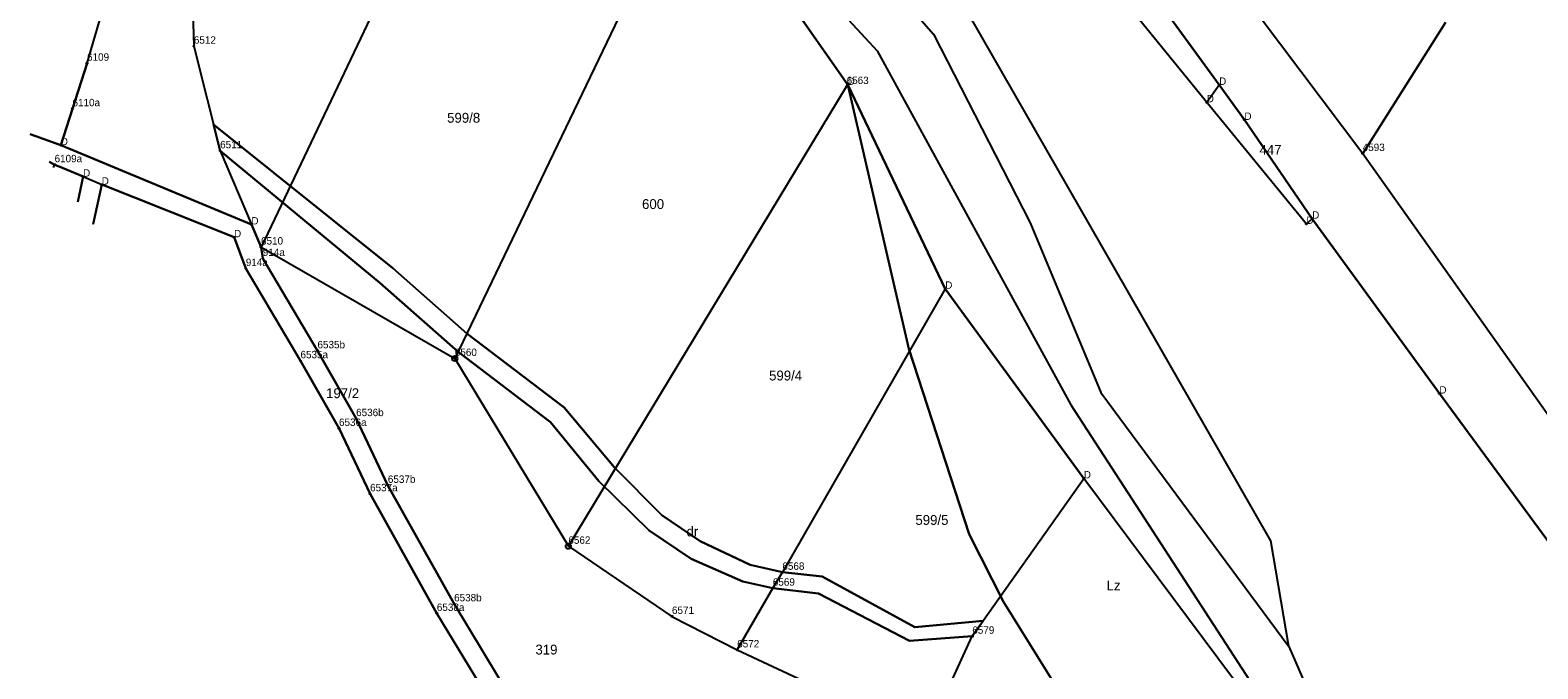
# Model space of a CAD drawing. Extents: x 7465393 to 7466459, y 5491258 to 5492404.
# Drawn here: x 7465732.5 to 7465961.5, y 5491598.3 to 5491695.3 of the extents above; entities that cross this region are included whole.
import ezdxf

# ---------------------------------------------------------------- set-up
doc = ezdxf.new("R2010")
doc.units = 0
for name, color, linetype in [('202-punkt graniczny', 7, 'Continuous'), ('202-punkt graniczny-Atr103', 7, 'Continuous'), ('203-punkt graniczny', 7, 'Continuous'), ('203-punkt graniczny-Atr103', 7, 'Continuous'), ('210-oznaczenie konturu użytku gruntowego', 7, 'Continuous'), ('211-numer działki ewidencyjnej', 7, 'Continuous'), ('217-kontur klasyfikacyjny', 7, 'Continuous'), ('218-kontur użytku gruntowego', 7, 'Continuous'), ('219-działka ewidencyjna', 7, 'Continuous')]:
    doc.layers.add(name, color=color, linetype=linetype)

# ---------------------------------------------------------------- blocks, each defined once
blk = doc.blocks.new('203')
blk.add_circle((0, 0), 0.09)
blk = doc.blocks.new('202')
blk.add_circle((0, 0), 0.4)

msp = doc.modelspace()

# ---------------------------------------------------------------- linework, layer by layer
at = {"layer": '217-kontur klasyfikacyjny'}
for points in [[(7465856.67, 5491687), (7465839.13, 5491712.1)], [(7465741.16, 5491690.28), (7465746.98, 5491710.25)], [(7465919.15, 5491697.5), (7465934.88, 5491676.57)], [(7465737.18, 5491677.85), (7465741.16, 5491690.28)], [(7465865.97, 5491646.94), (7465856.67, 5491687)], [(7465732.52, 5491679.49), (7465737.18, 5491677.85)], [(7465760.36, 5491681), (7465787.62, 5491659.17)], [(7465761.37, 5491676.99), (7465760.36, 5491681)], [(7465737.18, 5491677.85), (7465766.12, 5491665.8)], [(7465736.23, 5491674.88), (7465735.46, 5491675.31)], [(7465736.94, 5491674.58), (7465736.23, 5491674.88)], [(7465785.63, 5491656.92), (7465761.37, 5491676.99)], [(7465934.88, 5491676.57), (7465947.13, 5491659.3)], [(7465740.56, 5491673.06), (7465736.94, 5491674.58)], [(7465739.74, 5491669.23), (7465740.56, 5491673.06)], [(7465743.39, 5491671.85), (7465742.1, 5491665.87)], [(7465763.49, 5491663.86), (7465743.39, 5491671.85)], [(7465766.12, 5491665.8), (7465767.58, 5491662.37)], [(7465765.27, 5491659.12), (7465763.49, 5491663.86)], [(7465767.58, 5491662.37), (7465767.85, 5491660.64)], [(7465773.57, 5491645.11), (7465765.27, 5491659.12)], [(7465767.85, 5491660.64), (7465776.15, 5491646.63)], [(7465787.62, 5491659.17), (7465798.83, 5491649.24)], [(7465947.13, 5491659.3), (7465963.15, 5491636.73)], [(7465797.51, 5491646.48), (7465785.63, 5491656.92)], [(7465798.83, 5491649.24), (7465813.6, 5491638)], [(7465779.42, 5491634.84), (7465773.57, 5491645.11)], [(7465776.15, 5491646.63), (7465782.02, 5491636.32)], [(7465811.56, 5491635.78), (7465797.51, 5491646.48)], [(7465875.12, 5491618.79), (7465865.97, 5491646.94)], [(7465782.02, 5491636.32), (7465786.84, 5491626.19)], [(7465813.6, 5491638), (7465821.26, 5491628.88)], [(7465784.14, 5491624.91), (7465779.42, 5491634.84)], [(7465818.88, 5491626.83), (7465811.56, 5491635.78)], [(7465826.53, 5491619.32), (7465818.88, 5491626.83)], [(7465821.26, 5491628.88), (7465828.42, 5491621.66)], [(7465794.28, 5491606.75), (7465784.14, 5491624.91)], [(7465786.84, 5491626.19), (7465796.9, 5491608.21)], [(7465828.42, 5491621.66), (7465834.24, 5491617.72)], [(7465832.9, 5491615.04), (7465826.53, 5491619.32)], [(7465834.24, 5491617.72), (7465841.86, 5491614.12)], [(7465880.35, 5491608.51), (7465875.12, 5491618.79)], [(7465840.74, 5491611.57), (7465832.9, 5491615.04)], [(7465841.86, 5491614.12), (7465846.75, 5491612.99)], [(7465846.75, 5491612.99), (7465852.81, 5491612.35)], [(7465845.3, 5491610.58), (7465840.74, 5491611.57)], [(7465852.81, 5491612.35), (7465866.86, 5491604.67)], [(7465852.25, 5491609.79), (7465845.3, 5491610.58)], [(7465866.06, 5491602.58), (7465852.25, 5491609.79)], [(7465898.65, 5491579.07), (7465880.35, 5491608.51)], [(7465803.27, 5491591.89), (7465794.28, 5491606.75)], [(7465796.9, 5491608.21), (7465805.83, 5491593.45)], [(7465866.86, 5491604.67), (7465877.24, 5491605.61)], [(7465877.24, 5491605.61), (7465875.59, 5491603.28)], [(7465875.59, 5491603.28), (7465866.06, 5491602.58)]]:
    msp.add_lwpolyline(points, dxfattribs=at)
at = {"layer": '218-kontur użytku gruntowego'}
for points in [[(7465851.21, 5491715.81), (7465869.7, 5491694.71)], [(7465856.67, 5491687), (7465839.13, 5491712.1)], [(7465842.48, 5491712.43), (7465861.14, 5491692.18)], [(7465741.16, 5491690.28), (7465746.98, 5491710.25)], [(7465913.07, 5491687), (7465895.68, 5491710.95)], [(7465896.94, 5491659.61), (7465875.33, 5491697.27)], [(7465919.15, 5491697.5), (7465934.88, 5491676.57)], [(7465947.44, 5491696.48), (7465934.88, 5491676.57)], [(7465869.7, 5491694.71), (7465884.39, 5491666.06)], [(7465861.14, 5491692.18), (7465890.56, 5491638.43)], [(7465737.18, 5491677.85), (7465741.16, 5491690.28)], [(7465856.67, 5491687), (7465865.97, 5491646.94)], [(7465871.48, 5491656.04), (7465856.67, 5491687)], [(7465916.91, 5491681.68), (7465913.07, 5491687)], [(7465927.2, 5491666.68), (7465916.91, 5491681.68)], [(7465732.52, 5491679.49), (7465737.18, 5491677.85)], [(7465760.36, 5491681), (7465761.37, 5491676.99)], [(7465787.62, 5491659.17), (7465760.36, 5491681)], [(7465766.12, 5491665.8), (7465737.18, 5491677.85)], [(7465735.46, 5491675.31), (7465736.23, 5491674.88)], [(7465736.23, 5491674.88), (7465736.94, 5491674.58)], [(7465761.37, 5491676.99), (7465785.63, 5491656.92)], [(7465934.88, 5491676.57), (7465947.13, 5491659.3)], [(7465736.94, 5491674.58), (7465740.56, 5491673.06)], [(7465740.56, 5491673.06), (7465739.74, 5491669.23)], [(7465742.1, 5491665.87), (7465743.39, 5491671.85)], [(7465743.39, 5491671.85), (7465763.49, 5491663.86)], [(7465767.58, 5491662.37), (7465766.12, 5491665.8)], [(7465884.39, 5491666.06), (7465895.1, 5491640.28)], [(7465946.52, 5491640.13), (7465927.2, 5491666.68)], [(7465763.49, 5491663.86), (7465765.27, 5491659.12)], [(7465767.85, 5491660.64), (7465767.58, 5491662.37)], [(7465765.27, 5491659.12), (7465773.57, 5491645.11)], [(7465776.15, 5491646.63), (7465767.85, 5491660.64)], [(7465798.83, 5491649.24), (7465787.62, 5491659.17)], [(7465920.92, 5491617.77), (7465896.94, 5491659.61)], [(7465947.13, 5491659.3), (7465963.15, 5491636.73)], [(7465785.63, 5491656.92), (7465797.51, 5491646.48)], [(7465892.52, 5491627.25), (7465871.48, 5491656.04)], [(7465813.6, 5491638), (7465798.83, 5491649.24)], [(7465773.57, 5491645.11), (7465779.42, 5491634.84)], [(7465782.02, 5491636.32), (7465776.15, 5491646.63)], [(7465797.51, 5491646.48), (7465811.56, 5491635.78)], [(7465865.97, 5491646.94), (7465875.12, 5491618.79)], [(7465890.56, 5491638.43), (7465933.24, 5491572.65)], [(7465895.1, 5491640.28), (7465923.67, 5491601.71)], [(7465974.63, 5491601.95), (7465946.52, 5491640.13)], [(7465786.84, 5491626.19), (7465782.02, 5491636.32)], [(7465821.26, 5491628.88), (7465813.6, 5491638)], [(7465779.42, 5491634.84), (7465784.14, 5491624.91)], [(7465811.56, 5491635.78), (7465818.88, 5491626.83)], [(7465818.88, 5491626.83), (7465826.53, 5491619.32)], [(7465828.42, 5491621.66), (7465821.26, 5491628.88)], [(7465933.24, 5491572.65), (7465892.52, 5491627.25)], [(7465784.14, 5491624.91), (7465794.28, 5491606.75)], [(7465796.9, 5491608.21), (7465786.84, 5491626.19)], [(7465834.24, 5491617.72), (7465828.42, 5491621.66)], [(7465826.53, 5491619.32), (7465832.9, 5491615.04)], [(7465841.86, 5491614.12), (7465834.24, 5491617.72)], [(7465875.12, 5491618.79), (7465880.35, 5491608.51)], [(7465923.67, 5491601.71), (7465920.92, 5491617.77)], [(7465832.9, 5491615.04), (7465840.74, 5491611.57)], [(7465846.75, 5491612.99), (7465841.86, 5491614.12)], [(7465852.81, 5491612.35), (7465846.75, 5491612.99)], [(7465840.74, 5491611.57), (7465845.3, 5491610.58)], [(7465866.86, 5491604.67), (7465852.81, 5491612.35)], [(7465845.3, 5491610.58), (7465852.25, 5491609.79)], [(7465852.25, 5491609.79), (7465866.06, 5491602.58)], [(7465880.35, 5491608.51), (7465898.65, 5491579.07)], [(7465794.28, 5491606.75), (7465803.27, 5491591.89)], [(7465805.83, 5491593.45), (7465796.9, 5491608.21)], [(7465877.24, 5491605.61), (7465866.86, 5491604.67)], [(7465875.59, 5491603.28), (7465877.24, 5491605.61)], [(7465866.06, 5491602.58), (7465875.59, 5491603.28)], [(7465923.67, 5491601.71), (7465936.16, 5491572.97)]]:
    msp.add_lwpolyline(points, dxfattribs=at)
at = {"layer": '219-działka ewidencyjna'}
for points in [[(7465792.78, 5491715.23), (7465767.58, 5491662.37)], [(7465839.13, 5491712.1), (7465856.67, 5491687)], [(7465741.16, 5491690.28), (7465746.98, 5491710.25)], [(7465895.68, 5491710.95), (7465913.07, 5491687)], [(7465892.96, 5491706.79), (7465911.2, 5491684.35)], [(7465824.45, 5491702.61), (7465797.01, 5491645.45)], [(7465757.12, 5491701.58), (7465757.38, 5491692.88)], [(7465919.15, 5491697.5), (7465934.88, 5491676.57)], [(7465934.88, 5491676.57), (7465947.44, 5491696.48)], [(7465757.38, 5491692.88), (7465761.37, 5491676.99)], [(7465741.16, 5491690.28), (7465738.95, 5491683.38)], [(7465814.25, 5491616.94), (7465856.51, 5491686.74)], [(7465856.67, 5491687), (7465856.51, 5491686.74)], [(7465856.67, 5491687), (7465871.48, 5491656.04)], [(7465911.2, 5491684.35), (7465913.07, 5491687)], [(7465913.07, 5491687), (7465916.91, 5491681.68)], [(7465911.2, 5491684.35), (7465926.32, 5491665.89)], [(7465738.95, 5491683.38), (7465737.18, 5491677.85)], [(7465916.91, 5491681.68), (7465927.2, 5491666.68)], [(7465737.18, 5491677.85), (7465732.52, 5491679.49)], [(7465737.18, 5491677.85), (7465766.12, 5491665.8)], [(7465735.46, 5491675.31), (7465736.23, 5491674.88)], [(7465736.05, 5491674.46), (7465736.23, 5491674.88)], [(7465740.56, 5491673.06), (7465736.23, 5491674.88)], [(7465761.37, 5491676.99), (7465766.12, 5491665.8)], [(7465934.88, 5491676.57), (7465963.15, 5491636.73)], [(7465740.56, 5491673.06), (7465739.74, 5491669.23)], [(7465740.56, 5491673.06), (7465743.39, 5491671.85)], [(7465743.39, 5491671.85), (7465742.1, 5491665.87)], [(7465743.39, 5491671.85), (7465763.49, 5491663.86)], [(7465767.58, 5491662.37), (7465766.12, 5491665.8)], [(7465926.32, 5491665.89), (7465927.2, 5491666.68)], [(7465927.2, 5491666.68), (7465946.52, 5491640.13)], [(7465763.49, 5491663.86), (7465765.27, 5491659.12)], [(7465767.58, 5491662.37), (7465797.01, 5491645.45)], [(7465767.58, 5491662.37), (7465767.85, 5491660.64)], [(7465765.27, 5491659.12), (7465773.57, 5491645.11)], [(7465767.85, 5491660.64), (7465776.15, 5491646.63)], [(7465871.48, 5491656.04), (7465846.75, 5491612.99)], [(7465871.48, 5491656.04), (7465892.52, 5491627.25)], [(7465773.57, 5491645.11), (7465779.42, 5491634.84)], [(7465776.15, 5491646.63), (7465782.02, 5491636.32)], [(7465797.01, 5491645.45), (7465814.25, 5491616.94)], [(7465946.52, 5491640.13), (7465974.63, 5491601.95)], [(7465782.02, 5491636.32), (7465786.84, 5491626.19)], [(7465779.42, 5491634.84), (7465784.14, 5491624.91)], [(7465875.59, 5491603.28), (7465892.52, 5491627.25)], [(7465933.24, 5491572.65), (7465892.52, 5491627.25)], [(7465784.14, 5491624.91), (7465794.28, 5491606.75)], [(7465786.84, 5491626.19), (7465796.9, 5491608.21)], [(7465814.25, 5491616.94), (7465829.98, 5491606.3)], [(7465845.3, 5491610.58), (7465846.75, 5491612.99)], [(7465839.89, 5491601.21), (7465845.3, 5491610.58)], [(7465794.28, 5491606.75), (7465803.27, 5491591.89)], [(7465796.9, 5491608.21), (7465805.83, 5491593.45)], [(7465829.98, 5491606.3), (7465839.89, 5491601.21)], [(7465869.08, 5491589.12), (7465875.59, 5491603.28)], [(7465839.89, 5491601.21), (7465855.37, 5491593.99)]]:
    msp.add_lwpolyline(points, dxfattribs=at)

# ---------------------------------------------------------------- block references
at = {"layer": '202-punkt graniczny'}
for p in [(7465797.01, 5491645.45), (7465814.25, 5491616.94)]:
    msp.add_blockref('202', p, dxfattribs=at)
at = {"layer": '203-punkt graniczny'}
for p in [(7465757.38, 5491692.88), (7465741.16, 5491690.28), (7465856.51, 5491686.74), (7465856.67, 5491687), (7465913.07, 5491687), (7465911.2, 5491684.35), (7465738.95, 5491683.38), (7465916.91, 5491681.68), (7465737.18, 5491677.85), (7465761.37, 5491676.99), (7465736.23, 5491674.88), (7465934.88, 5491676.57), (7465740.56, 5491673.06), (7465743.39, 5491671.85), (7465766.12, 5491665.8), (7465926.32, 5491665.89), (7465927.2, 5491666.68), (7465763.49, 5491663.86), (7465767.58, 5491662.37), (7465765.27, 5491659.12), (7465767.85, 5491660.64), (7465871.48, 5491656.04), (7465773.57, 5491645.11), (7465776.15, 5491646.63), (7465946.52, 5491640.13), (7465782.02, 5491636.32), (7465779.42, 5491634.84), (7465892.52, 5491627.25), (7465784.14, 5491624.91), (7465786.84, 5491626.19), (7465846.75, 5491612.99), (7465845.3, 5491610.58), (7465794.28, 5491606.75), (7465796.9, 5491608.21), (7465829.98, 5491606.3), (7465875.59, 5491603.28), (7465839.89, 5491601.21)]:
    msp.add_blockref('203', p, dxfattribs=at)

# ---------------------------------------------------------------- texts
at = {"layer": '202-punkt graniczny-Atr103'}
for s, p in [('6560', (7465797.01, 5491645.83)), ('6562', (7465814.25, 5491617.32))]:
    msp.add_text(s, height=1.125, dxfattribs=at).set_placement(p)
at = {"layer": '203-punkt graniczny-Atr103'}
for s, height, p in [('6512', 1.125, (7465757.38, 5491693.25)), ('6109', 1.125, (7465741.16, 5491690.66)), ('6563', 1.125, (7465856.51, 5491687.12)), ('D', 1.12, (7465856.67, 5491687)), ('D', 1.12, (7465913.07, 5491687)), ('6110a', 1.125, (7465738.95, 5491683.75)), ('D', 1.12, (7465911.2, 5491684.35)), ('D', 1.12, (7465916.91, 5491681.68)), ('D', 1.12, (7465737.18, 5491677.85)), ('6511', 1.125, (7465761.37, 5491677.37)), ('4593', 1.125, (7465934.88, 5491676.95)), ('6109a', 1.125, (7465736.23, 5491675.25)), ('D', 1.12, (7465740.56, 5491673.06)), ('D', 1.12, (7465743.39, 5491671.85)), ('D', 1.12, (7465766.12, 5491665.8)), ('D', 1.12, (7465926.32, 5491665.89)), ('D', 1.12, (7465927.2, 5491666.68)), ('D', 1.12, (7465763.49, 5491663.86)), ('6510', 1.125, (7465767.58, 5491662.75)), ('914a', 1.125, (7465767.85, 5491661.02)), ('914a', 1.125, (7465765.27, 5491659.5)), ('D', 1.12, (7465871.48, 5491656.04)), ('6535b', 1.125, (7465776.15, 5491647)), ('6535a', 1.125, (7465773.57, 5491645.49)), ('D', 1.12, (7465946.52, 5491640.13)), ('6536a', 1.125, (7465779.42, 5491635.21)), ('6536b', 1.125, (7465782.02, 5491636.7)), ('6537b', 1.125, (7465786.84, 5491626.57)), ('D', 1.12, (7465892.52, 5491627.25)), ('6537a', 1.125, (7465784.14, 5491625.29)), ('6568', 1.125, (7465846.75, 5491613.37)), ('6569', 1.125, (7465845.3, 5491610.96)), ('6538b', 1.125, (7465796.9, 5491608.58)), ('6538a', 1.125, (7465794.28, 5491607.12)), ('6571', 1.125, (7465829.98, 5491606.67)), ('6579', 1.125, (7465875.59, 5491603.66)), ('6572', 1.125, (7465839.89, 5491601.58))]:
    msp.add_text(s, height=height, dxfattribs=at).set_placement(p)
at = {"layer": '210-oznaczenie konturu użytku gruntowego'}
for s, p in [('dr', (7465832.19, 5491618.44)), ('Lz', (7465895.98, 5491610.24))]:
    msp.add_text(s, height=1.5, dxfattribs=at).set_placement(p)
at = {"layer": '211-numer działki ewidencyjnej'}
for s, p in [('599/8', (7465795.84, 5491681.25)), ('447', (7465919.2, 5491676.39)), ('600', (7465825.44, 5491668.15)), ('599/4', (7465844.73, 5491642.12)), ('197/2', (7465777.46, 5491639.43)), ('599/5', (7465866.95, 5491620.19)), ('319', (7465809.25, 5491600.51))]:
    msp.add_text(s, height=1.5, dxfattribs=at).set_placement(p)

doc.saveas('drawing.dxf')
